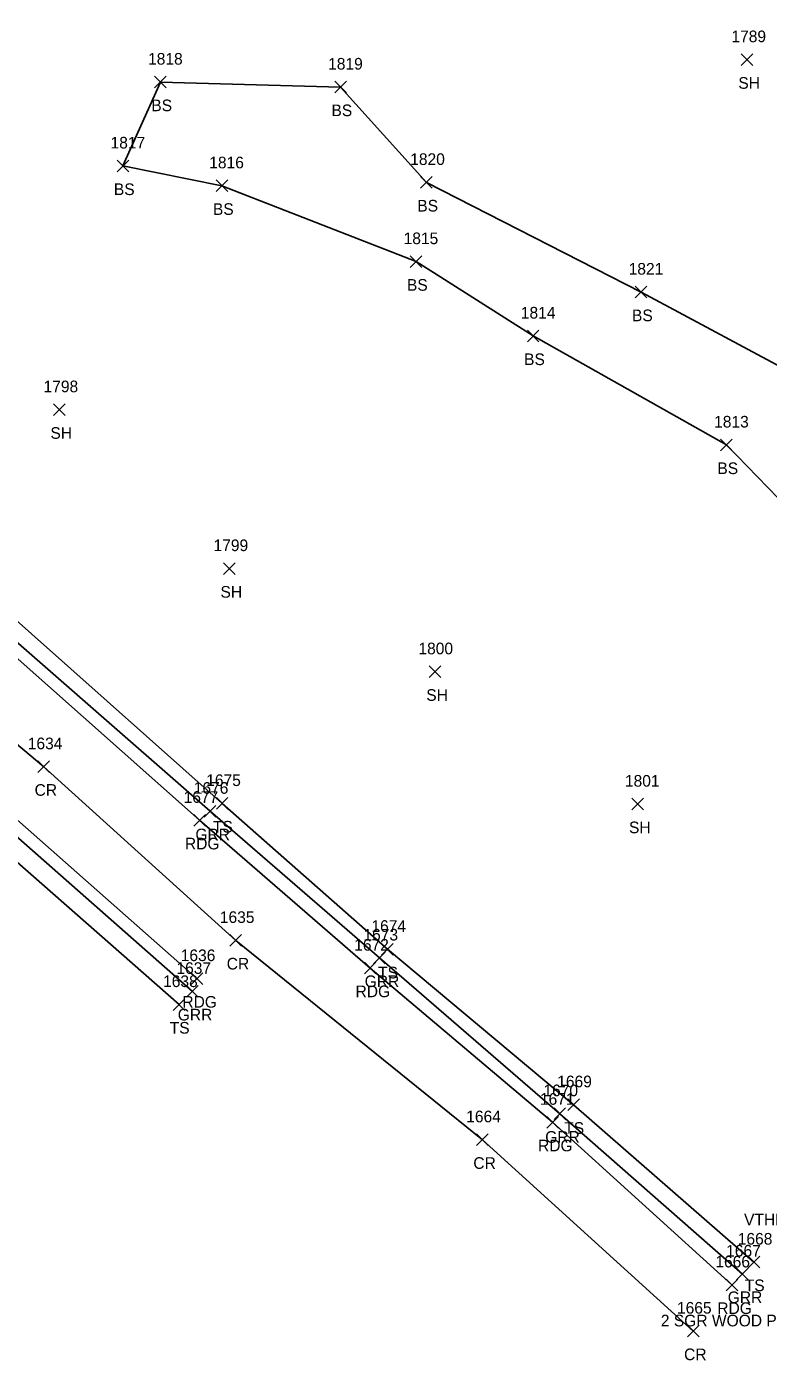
# Model space of a CAD drawing. Extents: x 1629176 to 1637209, y 606063 to 610167.
# Drawn here: x 1629948.1 to 1630075.4, y 606610.6 to 606839.8 of the extents above; entities that cross this region are included whole.
import ezdxf

# ---------------------------------------------------------------- set-up
doc = ezdxf.new("R2010")
doc.units = 0
for name, color, linetype in [('L_A', 7, 'Continuous'), ('L_I', 7, 'Continuous'), ('L_TIC', 7, 'Continuous'), ('LELB', 7, 'Continuous'), ('M_C', 7, 'Continuous'), ('P_A', 7, 'Continuous'), ('P_I', 7, 'Continuous'), ('P_TIC', 7, 'Continuous'), ('PEU', 7, 'Continuous'), ('PRC', 7, 'Continuous'), ('R_A', 7, 'Continuous'), ('R_C', 7, 'Continuous'), ('R_I', 7, 'Continuous'), ('R_TIC', 7, 'Continuous'), ('RGR', 7, 'Continuous')]:
    doc.layers.add(name, color=color, linetype=linetype)

msp = doc.modelspace()

# ---------------------------------------------------------------- linework, layer by layer
at = {"layer": 'L_TIC'}
for points in [[(1630070.81, 606833.11), (1630072.81, 606835.11)], [(1630072.81, 606833.11), (1630070.81, 606835.11)], [(1629970.03, 606829.25), (1629972.03, 606831.25)], [(1629972.03, 606829.25), (1629970.03, 606831.25)], [(1630000.97, 606828.4), (1630002.97, 606830.4)], [(1630002.97, 606828.4), (1630000.97, 606830.4)], [(1629963.6, 606814.84), (1629965.6, 606816.84)], [(1629965.6, 606814.84), (1629963.6, 606816.84)], [(1629980.61, 606811.43), (1629982.61, 606813.43)], [(1629982.61, 606811.43), (1629980.61, 606813.43)], [(1630015.72, 606812.01), (1630017.72, 606814.01)], [(1630017.72, 606812.01), (1630015.72, 606814.01)], [(1630013.94, 606798.4), (1630015.94, 606800.4)], [(1630015.94, 606798.4), (1630013.94, 606800.4)], [(1630052.59, 606793.16), (1630054.59, 606795.16)], [(1630054.59, 606793.16), (1630052.59, 606795.16)], [(1630034.06, 606785.62), (1630036.06, 606787.62)], [(1630036.06, 606785.62), (1630034.06, 606787.62)], [(1629952.65, 606772.95), (1629954.65, 606774.95)], [(1629954.65, 606772.95), (1629952.65, 606774.95)], [(1630067.26, 606766.89), (1630069.26, 606768.89)], [(1630069.26, 606766.89), (1630067.26, 606768.89)], [(1629981.86, 606745.65), (1629983.86, 606747.65)], [(1629983.86, 606745.65), (1629981.86, 606747.65)], [(1630017.21, 606727.92), (1630019.21, 606729.92)], [(1630019.21, 606727.92), (1630017.21, 606729.92)], [(1629980.64, 606705.28), (1629982.64, 606707.28)], [(1629982.64, 606705.28), (1629980.64, 606707.28)], [(1630052.03, 606705.17), (1630054.03, 606707.17)], [(1630054.03, 606705.17), (1630052.03, 606707.17)], [(1630009.01, 606680.22), (1630011.01, 606682.22)], [(1630011.01, 606680.22), (1630009.01, 606682.22)], [(1629973.23, 606670.73), (1629975.23, 606672.73)], [(1629975.23, 606670.73), (1629973.23, 606672.73)], [(1630040.99, 606653.51), (1630042.99, 606655.51)], [(1630042.99, 606653.51), (1630040.99, 606655.51)], [(1630071.99, 606626.47), (1630073.99, 606628.47)], [(1630073.99, 606626.47), (1630071.99, 606628.47)]]:
    msp.add_lwpolyline(points, dxfattribs=at)
at = {"layer": 'LELB'}
for points in [[(1630072.99, 606627.47), (1630041.99, 606654.51), (1630010.01, 606681.22), (1629981.64, 606706.28), (1629935.83, 606746.98), (1629900.42, 606776.48), (1629884.89, 606790.02), (1629879.22, 606802.61), (1629877.3, 606811.37), (1629877.5, 606819.88), (1629880.93, 606830.79), (1629891.36, 606847.82), (1629915.71, 606875.42), (1629940.9, 606902.48), (1629963.67, 606912.99), (1630002.21, 606903.33), (1630044.25, 606889.35), (1630091.41, 606872.59)], [(1630091.33, 606744.1), (1630068.26, 606767.89), (1630035.06, 606786.62), (1630014.94, 606799.4), (1629981.61, 606812.43), (1629964.6, 606815.84), (1629971.03, 606830.25), (1630001.97, 606829.4), (1630016.72, 606813.01), (1630053.59, 606794.16), (1630081.62, 606779.15)], [(1629974.23, 606671.73), (1629944.56, 606697.88), (1629917.84, 606720.26), (1629895.86, 606740.8), (1629872.45, 606761.2), (1629853.73, 606776.41), (1629836.55, 606788.97), (1629824.22, 606793.63), (1629808.76, 606792.78), (1629777.19, 606783.69), (1629732.57, 606770.35)]]:
    msp.add_lwpolyline(points, dxfattribs=at)
at = {"layer": 'P_TIC'}
for points in [[(1629949.99, 606711.6), (1629951.99, 606713.6)], [(1629951.99, 606711.6), (1629949.99, 606713.6)], [(1629976.76, 606702.39), (1629978.76, 606704.39)], [(1629978.76, 606702.39), (1629976.76, 606704.39)], [(1629982.98, 606681.75), (1629984.98, 606683.75)], [(1629984.98, 606681.75), (1629982.98, 606683.75)], [(1630006.06, 606676.99), (1630008.06, 606678.99)], [(1630008.06, 606676.99), (1630006.06, 606678.99)], [(1629976.31, 606675.19), (1629978.31, 606677.19)], [(1629978.31, 606675.19), (1629976.31, 606677.19)], [(1630037.4, 606650.5), (1630039.4, 606652.5)], [(1630039.4, 606650.5), (1630037.4, 606652.5)], [(1630025.35, 606647.49), (1630027.35, 606649.49)], [(1630027.35, 606647.49), (1630025.35, 606649.49)], [(1630068.19, 606622.55), (1630070.19, 606624.55)], [(1630070.19, 606622.55), (1630068.19, 606624.55)], [(1630061.55, 606614.61), (1630063.55, 606616.61)], [(1630063.55, 606614.61), (1630061.55, 606616.61)]]:
    msp.add_lwpolyline(points, dxfattribs=at)
at = {"layer": 'PEU'}
for points in [[(1630069.19, 606623.55), (1630038.4, 606651.5), (1630007.06, 606677.99), (1629977.76, 606703.39), (1629931.71, 606744.23), (1629897.14, 606772.5)], [(1629882.91, 606759.19), (1629916.47, 606729.34), (1629944.44, 606705.22), (1629977.31, 606676.19)]]:
    msp.add_lwpolyline(points, dxfattribs=at)
at = {"layer": 'PRC'}
msp.add_lwpolyline([(1629847.76, 606817.22), (1629856.43, 606802.15), (1629871.31, 606783.29), (1629889.77, 606765.03), (1629921.75, 606737.15), (1629950.99, 606712.6), (1629983.98, 606682.75), (1630026.35, 606648.49), (1630062.55, 606615.61)], dxfattribs=at)
at = {"layer": 'R_TIC'}
for points in [[(1629978.55, 606703.95), (1629980.55, 606705.95)], [(1629980.55, 606703.95), (1629978.55, 606705.95)], [(1630007.64, 606678.73), (1630009.64, 606680.73)], [(1630009.64, 606678.73), (1630007.64, 606680.73)], [(1629975.52, 606672.99), (1629977.52, 606674.99)], [(1629977.52, 606672.99), (1629975.52, 606674.99)], [(1630038.64, 606651.97), (1630040.64, 606653.97)], [(1630040.64, 606651.97), (1630038.64, 606653.97)], [(1630070, 606624.42), (1630072, 606626.42)], [(1630072, 606624.42), (1630070, 606626.42)]]:
    msp.add_lwpolyline(points, dxfattribs=at)
at = {"layer": 'RGR'}
for points in [[(1629610.69, 606767.66), (1629614.78, 606771.08), (1629618.2, 606772.52), (1629623.02, 606773.09), (1629651.93, 606771.73), (1629678.65, 606772.42), (1629701.28, 606773.86), (1629724.79, 606776.82), (1629746.85, 606781.44), (1629773.74, 606788.69), (1629807.56, 606798.03), (1629819.63, 606798.3), (1629831.2, 606794.55), (1629845.84, 606786.32), (1629881.37, 606757.13), (1629915.43, 606727.34), (1629943.21, 606703.31), (1629976.52, 606673.99)], [(1630071, 606625.42), (1630039.64, 606652.97), (1630008.64, 606679.73), (1629979.55, 606704.95), (1629933.36, 606745.32), (1629899.17, 606774.69), (1629881.78, 606789.58), (1629877.23, 606797.29)]]:
    msp.add_lwpolyline(points, dxfattribs=at)

# ---------------------------------------------------------------- texts
at = {"layer": 'L_A'}
for s, p in [('SH', (1630070.3, 606829.11)), ('BS', (1629969.47, 606825.25)), ('BS', (1630000.41, 606824.4)), ('BS', (1629963.04, 606810.84)), ('BS', (1629980.05, 606807.43)), ('BS', (1630015.16, 606808.01)), ('BS', (1630013.38, 606794.4)), ('BS', (1630052.03, 606789.16)), ('BS', (1630033.5, 606781.62)), ('SH', (1629952.14, 606768.95)), ('BS', (1630066.7, 606762.89)), ('SH', (1629981.35, 606741.65)), ('SH', (1630016.7, 606723.92)), ('TS', (1629980.05, 606701.28)), ('SH', (1630051.52, 606701.17)), ('TS', (1630008.42, 606676.22)), ('TS', (1629972.63, 606666.73)), ('TS', (1630040.4, 606649.51)), ('TS', (1630071.4, 606622.47))]:
    msp.add_text(s, height=2, dxfattribs=at).set_placement(p)
at = {"layer": 'L_I'}
for s, p in [('1789', (1630069.11, 606837.11)), ('1818', (1629968.91, 606833.25)), ('1819', (1629999.84, 606832.4)), ('1817', (1629962.47, 606818.84)), ('1820', (1630013.94, 606816.01)), ('1816', (1629979.42, 606815.43)), ('1815', (1630012.81, 606802.4)), ('1821', (1630051.46, 606797.16)), ('1814', (1630032.94, 606789.62)), ('1798', (1629950.96, 606776.95)), ('1813', (1630066.14, 606770.89)), ('1799', (1629980.16, 606749.65)), ('1800', (1630015.35, 606731.92)), ('1675', (1629978.9, 606709.28)), ('1801', (1630050.82, 606709.17)), ('1674', (1630007.27, 606684.22)), ('1638', (1629971.49, 606674.73)), ('1669', (1630039.19, 606657.51)), ('1668', (1630070.2, 606630.47))]:
    msp.add_text(s, height=2, dxfattribs=at).set_placement(p)
at = {"layer": 'M_C'}
msp.add_text('VTHD CONCRETE', height=2, dxfattribs=at).set_placement((1630071.28, 606633.77))
at = {"layer": 'P_A'}
for s, p in [('CR', (1629949.42, 606707.6)), ('RDG', (1629975.24, 606698.39)), ('CR', (1629982.42, 606677.75)), ('RDG', (1630004.55, 606672.99)), ('RDG', (1629974.8, 606671.19)), ('RDG', (1630035.89, 606646.5)), ('CR', (1630024.78, 606643.49)), ('RDG', (1630066.68, 606618.55)), ('CR', (1630060.98, 606610.61))]:
    msp.add_text(s, height=2, dxfattribs=at).set_placement(p)
at = {"layer": 'P_I'}
for s, p in [('1634', (1629948.25, 606715.6)), ('1677', (1629975.02, 606706.39)), ('1635', (1629981.24, 606685.75)), ('1672', (1630004.32, 606680.99)), ('1636', (1629974.52, 606679.19)), ('1671', (1630036.22, 606654.5)), ('1664', (1630023.56, 606651.49)), ('1666', (1630066.35, 606626.55)), ('1665', (1630059.76, 606618.61))]:
    msp.add_text(s, height=2, dxfattribs=at).set_placement(p)
at = {"layer": 'R_A'}
for p in [(1629977.04, 606699.95), (1630006.12, 606674.73), (1629974.01, 606668.99), (1630037.13, 606647.97), (1630068.48, 606620.42)]:
    msp.add_text('GRR', height=2, dxfattribs=at).set_placement(p)
at = {"layer": 'R_C'}
msp.add_text('2 SGR WOOD POST', height=2, dxfattribs=at).set_placement((1630056.99, 606616.42))
at = {"layer": 'R_I'}
for s, p in [('1676', (1629976.75, 606707.95)), ('1673', (1630005.9, 606682.73)), ('1637', (1629973.78, 606676.99)), ('1670', (1630036.82, 606655.97)), ('1667', (1630068.21, 606628.42))]:
    msp.add_text(s, height=2, dxfattribs=at).set_placement(p)

doc.saveas('drawing.dxf')
